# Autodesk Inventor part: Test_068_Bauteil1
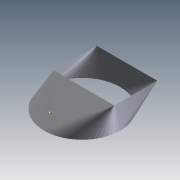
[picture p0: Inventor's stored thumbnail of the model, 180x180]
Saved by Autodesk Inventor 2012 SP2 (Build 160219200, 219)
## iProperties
Created: 2013-11
Part Number: Test_068_Bauteil1
Material: Default
Document SubType Name: Blech
Designer: Drescher
Density: 1 g/cm^3
Flat Pattern Width: 217.521 cm
Flat Pattern Length: 444.487 cm
Flat Pattern Area: 96685.4 cm^2
Sheet Metal Rule: Standard
Sheet Metal Width: 2175,212 mm
Sheet Metal Length: 4444,872 mm
Sheet Metal Area: 9668537,675 mm^2
RuleStatus: InUse
Author: Drescher
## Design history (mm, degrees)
sketch "Skizze1"
  geometry: C1 r 750 at (0, 0); 1 further point
  constraints: 1 centre point, 1 coincident
  dimensions: "d0" = 1500 diameter of C1
sketch "Skizze2"
  geometry: L1 (0, 0)-(0, 800); L2 (0, 0)-(-461.88, 800); L3 (0, 800)-(-461.88, 800)
  constraints: 6 end point, 1 perpendicular, 1 vertical
  dimensions: "d1" = 30 deg angle of L2 L1; "d2" = 800 distance of L1.start L1.end
workplane "Arbeitsebene1"
node "Übergangslasche1"
  sketch "Skizze3"
    geometry: L1 (-138.12, 425)-(1061.88, 425); L2 (1061.88, 425)-(1061.88, -425); L3 (1061.88, -425)-(-138.12, -425); L4 (-138.12, -425)-(-138.12, 425); L5 (-138.12, 425)-(1061.88, -425); L6 (-138.12, -425)-(1061.88, 425); 3 further points
    constraints: 12 end point, 2 parallel, 1 coincident, 1 horizontal, 1 midpoint, 1 perpendicular
    dimensions: "d3" = 850 distance of L1.end L2.end; "d4" = 1200 distance of L1.start L1.end
sketch "Skizze4"
  geometry: 1 further point
feature "Auftrennung1" dims "d11" = 0.5 (= Abstandsgröße)
node "Volumenkörper1"
feature "Biegung1" dims "d6" = 0.5 (= Biegeradius), "d7" = 0.5 (= BreiteBiegungsfreistellung), "d8" = 0.25 (= TiefeBiegungsfreistellung), "d9" = 1 (= MinimalRest), "d10" = 0.5 (= Biegeradius), "Stärke" = 0.5, "AbstandVerbindung" = 0.01
feature "Definition1"
other parameters: "KFaktor" = 4.4, "Biegeradius" = 0.5 (= Stärke), "BreiteBiegungsfreistellung" = 0.5 (= Stärke), "TiefeBiegungsfreistellung" = 0.25 (= 0.5 x Stärke), "GrößeEckenfreistellung" = 2 (= 4 x Stärke), "MinimalRest" = 1 (= 2 x Stärke), "Übergangsradius" = 0.5 (= Biegeradius), "JacobiRadiusGröße" = 0.5 (= Stärke), "Abstandsgröße" = 0.5 (= Stärke), "d5" = 1, "Abstandsgröße" = 0.5, "Biegeradius" = 0.5, "BreiteBiegungsfreistellung" = 0.5, "GrößeEckenfreistellung" = 2, "JacobiRadiusGröße" = 0.5, "MinimalRest" = 1, "Stärke" = 0.5, "TiefeBiegungsfreistellung" = 0.25, "Übergangsradius" = 0.5
